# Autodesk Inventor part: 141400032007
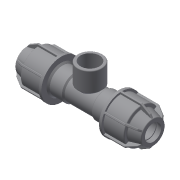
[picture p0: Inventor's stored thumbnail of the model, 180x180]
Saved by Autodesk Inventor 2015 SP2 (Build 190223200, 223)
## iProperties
Created: 2017-08
Part Number: 141400032007
Material: Generic
Description: PLASSON L.14 TEE FEMALE ADAPTOR (SILVER) 32 x 3/4" x 32
Document SubType Name: Modeling
Designer: KIM
Density: 1 g/cm^3
Appearance: Default
Author: KIM
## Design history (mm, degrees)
derived "141400.ipt"
feature "Solid1::141400.ipt"
feature "Solid2::141400.ipt"
tag "TaggingFeature1"
body "Solid1"
other parameters: "d1" = 32, "d2" = 56, "d4" = 15 deg, "d5" = 36.96, "d6" = 12.1968, "d10" = 61, "d16" = 32.64, "d17" = 2.8, "d22" = 51.2, "d24" = 2.8, "d25" = 54.9, "d26" = 45.75, "d27" = 2.8, "d28" = 135 deg, "d29" = 1.68, "d31" = 1.6, "d46" = 150 deg, "d49" = 3.05, "d50" = 0, "d58" = 0.96, "d61" = 360 deg, "d63" = 28.8, "d64" = 75, "d80" = 46.08, "d81" = 2.56, "d84" = 2.8, "d94" = 52, "d95" = 24.117, "d96" = 31.3521, "d97" = 19, "d98" = 19.2, "d99" = 25.08168, "d100" = 135 deg, "d108" = 1.6, "d111" = 0, "d_" = 32, "G_" = 24.117, "E_" = 61, "l_" = 56, "l_2" = 19, "A_" = 52
